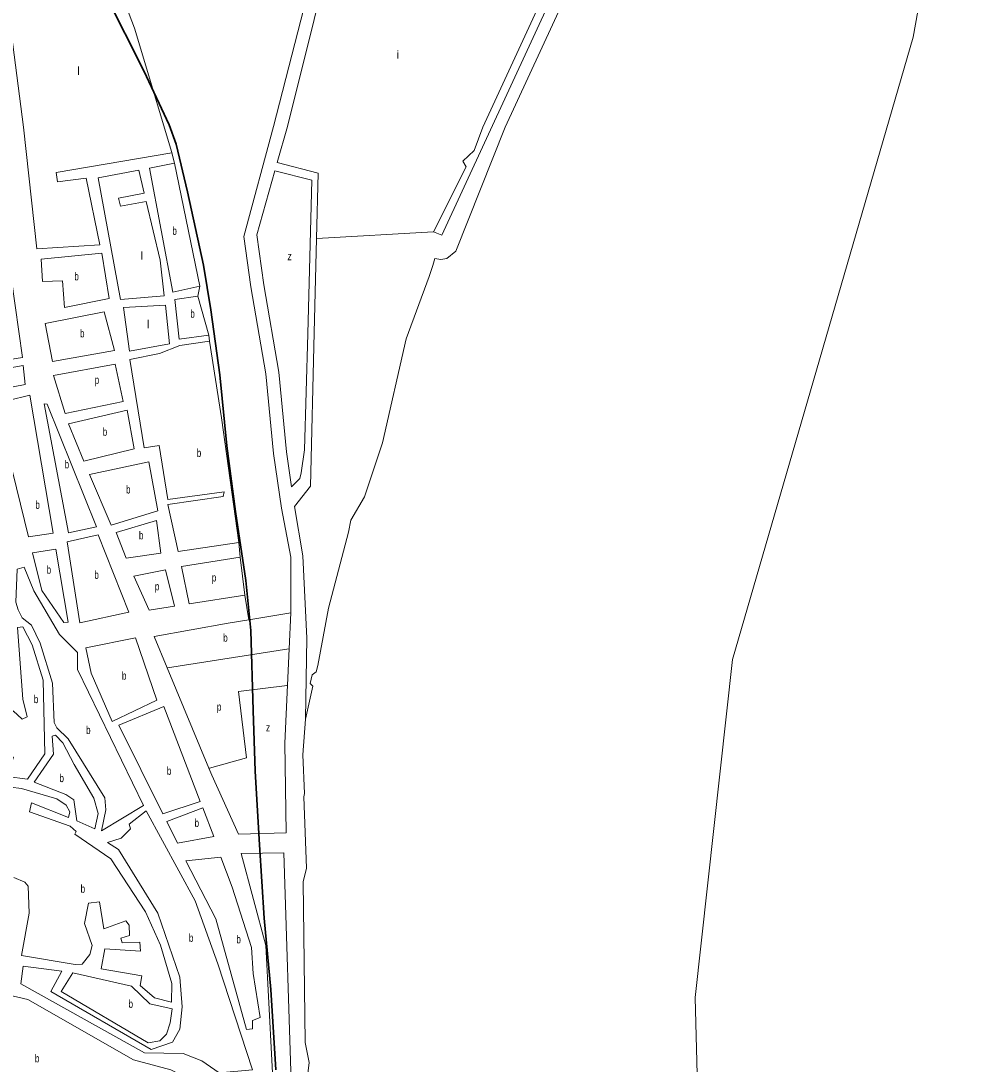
# Model space of a CAD drawing. Extents: x 639657 to 671642, y 222838 to 252123.
# Drawn here: x 649246 to 650431, y 230829 to 232133 of the extents above; entities that cross this region are included whole.
import ezdxf

# ---------------------------------------------------------------- set-up
doc = ezdxf.new("R2010")
doc.units = 0
doc.header["$LTSCALE"] = 4
for name, color, linetype, lineweight in [('1', 7, 'Continuous', 13), ('21', 7, 'Continuous', 13), ('5', 7, 'Continuous', 13), ('57', 7, 'Continuous', 35)]:
    doc.layers.add(name, color=color, linetype=linetype, lineweight=lineweight)
doc.layers.add('7', color=7, linetype='Continuous')

msp = doc.modelspace()

# ---------------------------------------------------------------- linework, layer by layer
at = {"layer": '1'}
for p, q in [((649438.357, 231955.126), (649435.192, 231967.793)), ((649541.28, 231865.64), (649563.936, 231945.516)), ((649470.009, 231801.543), (649467.77, 231788.97)), ((649482.18, 231732.54), (649445.05, 231727.09)), ((649481.26, 231740.27), (649482.18, 231732.54)), ((649257.71, 231665.2), (649286.921, 231492.626)), ((649256.111, 231487.884), (649286.921, 231492.626)), ((649260.979, 231468.111), (649290.307, 231472.624)), ((649443.105, 231469.834), (649519.069, 231480.917)), ((649519.069, 231480.917), (649520.652, 231462.709)), ((649526.191, 231415.209), (649456.923, 231404.194)), ((649526.191, 231415.209), (649531.321, 231384.416)), ((649259.79, 231377.8), (649270.686, 231355.212)), ((649424.077, 231141.872), (649470.646, 231157.402)), ((649428.786, 231132.38), (649473.78, 231149.261)), ((649246.529, 230929.234), (649401.026, 230842.89)), ((649409.489, 230847.242), (649284.125, 230919.807))]:
    msp.add_line(p, q, dxfattribs=at)
for points in [[(649762.3, 231869.13), (649772.4, 231864.93), (649940.18, 232227.89), (649998.36, 232408.27), (649997.95, 232423.52), (650058.51, 232619.37), (650064.55, 232643), (650104.58, 232932.12), (650113.04, 233010.96), (650175.02, 233792.05), (650190.2, 233935.97), (650200.75, 233955.07), (650211.5, 233964.3), (650215.81, 233978.25), (650212.82, 233991.15), (650207.837, 233999.334), (650219.35, 234019.81), (650224.822, 234038.14)], [(649702.77, 232544.411), (649668.79, 232416.28), (649562.38, 232001.06), (649525.091, 231863.401)], [(649435.192, 231967.793), (649290.77, 231943.33), (649292.43, 231931.86), (649328.02, 231936.28), (649345.19, 231853.16), (649266.36, 231847.82), (649249.9, 231999.94), (649221.67, 232216.71), (649212.68, 232270.71), (649191.78, 232361.07), (649194.31, 232402.14)], [(649566.832, 231955.727), (649579.69, 232001.06), (649679.95, 232404.23), (649852.47, 232394.09)], [(649877.62, 232406.51), (649979.89, 232407.87), (649983.96, 232397.76), (649931.38, 232233.48), (649823.94, 232000.28), (649812.92, 231970.91), (649798.63, 231957.69), (649802.98, 231950.42), (649762.3, 231869.13)], [(649438.357, 231955.126), (649407.38, 231948.77), (649436.35, 231793.89), (649470.009, 231801.543)], [(649566.832, 231955.727), (649617.981, 231942.459), (649616.022, 231860.839)], [(649584.72, 231550.58), (649595.034, 231560.876), (649596.74, 231568.11), (649600.81, 231596.95), (649605.24, 231741.89), (649610.068, 231933.751), (649563.936, 231945.516)], [(649572.085, 231523.788), (649562.183, 231592.174), (649552.709, 231691.694), (649533.778, 231800.601), (649525.091, 231863.401)], [(649584.72, 231550.58), (649578.415, 231594.121), (649568.919, 231693.871), (649549.928, 231803.121), (649541.28, 231865.64)], [(649616.022, 231860.839), (649613.19, 231742.81), (649608.486, 231551.376), (649588.26, 231526.13)], [(649481.26, 231740.27), (649444.12, 231735.04), (649438.79, 231784.66), (649467.77, 231788.97)], [(649419.283, 231602.27), (649400.72, 231599.46), (649382.65, 231709.83), (649419.77, 231717), (649445.05, 231727.09)], [(649256.111, 231487.884), (649225.91, 231610.56), (649230.69, 231658.54), (649257.71, 231665.2)], [(649419.283, 231602.27), (649430.03, 231534.77), (649500.44, 231544.14), (649499.19, 231538.54), (649430.08, 231528.54), (649443.105, 231469.834)], [(649583.954, 231393.038), (649583.648, 231462.728), (649572.085, 231523.788)], [(649602.2, 231260.14), (649603.736, 231361.371), (649598.988, 231464.287), (649588.26, 231526.13)], [(649290.307, 231472.624), (649305.75, 231381.39), (649300.38, 231380.92), (649272.55, 231421.11), (649260.979, 231468.111)], [(649520.652, 231462.709), (649447.061, 231450.834), (649456.923, 231404.194)], [(649294.91, 231365.83), (649262.89, 231420.39), (649250.62, 231450.17), (649241.82, 231447.74), (649240.22, 231406.45), (649243.09, 231396.59), (649248.11, 231386.95), (649259.79, 231377.8)], [(649583.954, 231393.038), (649581.831, 231348.027), (649579.682, 231302.45)], [(649429.416, 231324.306), (649413.12, 231363.53), (649505.4, 231380.17), (649531.321, 231384.416)], [(649399.55, 231152.37), (649347.37, 231120.37), (649352.75, 231146.84), (649351.34, 231161.66), (649305.62, 231235.66), (649291.54, 231249.31), (649288.27, 231255.94), (649285.94, 231304.93), (649270.686, 231355.212)], [(649294.91, 231365.83), (649317.23, 231343.43), (649317.39, 231322.37), (649399.55, 231152.37)], [(649518.48, 231116.29), (649485.21, 231190.01), (649481.543, 231198.836), (649429.416, 231324.306)], [(649579.682, 231302.45), (649576.28, 231230.29), (649578.03, 231117.89), (649518.48, 231116.29)], [(649470.646, 231157.402), (649425, 231275.94), (649369.09, 231252.71), (649424.077, 231141.872)], [(649191.96, 231179.96), (649247.24, 231173.3), (649291.39, 231160.76), (649303.06, 231152.47), (649307.64, 231144.12), (649305.98, 231137.02), (649259.85, 231155.35), (649257.14, 231144.15), (649308, 231126.5), (649315.79, 231119.9), (649314.1, 231116.24), (649358.83, 231085.43), (649402.12, 231019.16), (649420.93, 230977.84), (649435.28, 230929.82), (649434.61, 230906.39), (649413.51, 230911.81), (649395.76, 230927.14), (649397.6, 230939.19), (649347.03, 230948.03), (649351.34, 230973.2), (649396.06, 230970.33), (649395.33, 230981.5), (649372.99, 230980.68), (649371.22, 230986.25), (649382.37, 230989.56), (649381.84, 231002.67), (649377.49, 231008.22), (649350.28, 230998.12), (649344.8, 231032), (649331.11, 231030.25), (649325.95, 231004.59), (649335.62, 230977.16), (649332.49, 230965.96), (649323.13, 230953.85), (649314.33, 230953.35), (649247.4, 230964.86), (649256.86, 231017.79), (649255.52, 231051.31), (649251.4, 231056.43), (649237.81, 231062.34)], [(649464.11, 231032.97), (649403.26, 231145.74), (649381.69, 231129.02), (649383.67, 231123.23), (649371.94, 231111.54), (649354.58, 231106.03), (649368.4, 231097.33), (649417.82, 231017.78), (649445.32, 230937.63), (649447.98, 230900.48), (649444.98, 230872.74), (649435.87, 230856.34), (649409.489, 230847.242)], [(649428.786, 231132.38), (649442.26, 231105.22), (649487.54, 231113.53), (649473.78, 231149.261)], [(649567.46, 230690.72), (649552.53, 230977.3), (649521.71, 231092.02), (649575.25, 231092.998), (649584.745, 230793.748), (649599.555, 230443.052)], [(649401.026, 230842.89), (649449.31, 230842.05), (649472.8, 230833), (649494.2, 230817.92), (649535.85, 230821.9), (649492.68, 230954.34), (649464.11, 231032.97)], [(649246.529, 230929.234), (649249.44, 230951.55), (649297.711, 230945.357), (649284.125, 230919.807)], [(649466.79, 230805.67), (649433.78, 230821.95), (649387.27, 230834.25), (649255.36, 230909.7), (649204.99, 230921.33), (649151.23, 230925.2), (649143.7, 230873.15), (649119.54, 230804.2), (649146.68, 230796.03)]]:
    msp.add_lwpolyline(points, dxfattribs=at)
for points in [[(649400.76, 231917.62), (649393.99, 231946.29), (649343.24, 231936.8), (649370.88, 231784.56), (649425.64, 231789.07), (649420.56, 231833.75), (649403.22, 231907.22), (649371.15, 231901.31), (649368.53, 231911.5)], [(649347.64, 231842.43), (649272.05, 231834.96), (649273.56, 231807.02), (649298.7, 231808.08), (649300.9, 231774.76), (649356.9, 231785.74)], [(649248.32, 231712), (649234.65, 231809.51), (649138.69, 231796.29), (649120.43, 231768.63), (649130.98, 231694.72), (649144.204, 231654.694), (649199.595, 231674.486), (649195.639, 231703.778)], [(649382.14, 231720.14), (649374.61, 231774.7), (649427.02, 231777.47), (649432.13, 231729.35)], [(649350.77, 231769.26), (649363.43, 231720.78), (649285.989, 231707.244), (649276.66, 231754.84)], [(649249.284, 231702.137), (649251.821, 231678.444), (649224.125, 231672.902), (649218.586, 231696.653)], [(649287.186, 231689.771), (649364.186, 231703.778), (649374.472, 231657.069), (649301.673, 231642.027)], [(649275.42, 231654.16), (649305.93, 231493.17), (649341.12, 231500.54), (649279.51, 231653.77)], [(649306.14, 231629.46), (649325.21, 231582.53), (649388.27, 231597.86), (649379.5, 231646.16)], [(649359.15, 231502.61), (649332.22, 231565.82), (649406.44, 231581.88), (649417.46, 231520.7)], [(649378.18, 231461.28), (649365.67, 231493.64), (649415.84, 231508.43), (649421.32, 231467.63)], [(649304.52, 231481.76), (649320.15, 231380.43), (649381.51, 231394.02), (649343.13, 231490.66)], [(649438.463, 231401.259), (649406.705, 231396.209), (649387.714, 231438.959), (649427.279, 231446.876)], [(649248.85, 231375.35), (649242.41, 231374.87), (649249.14, 231285.3), (649254.26, 231262.98), (649248.26, 231260.14), (649237.01, 231270.37), (649222.77, 231250.27), (649194.64, 231193.74), (649219.17, 231190.28), (649227.34, 231216.35), (649237.47, 231212.77), (649229.49, 231188.64), (649254.88, 231184.97), (649276.55, 231216.73), (649274.31, 231308.71), (649260.63, 231353.09)], [(649416.55, 231283.82), (649360.68, 231257.37), (649334.19, 231317.56), (649327.5, 231349.1), (649389.93, 231361.63)], [(649289.68, 231240.05), (649285.61, 231238.73), (649287.29, 231216.39), (649263.29, 231181.38), (649302.53, 231165.79), (649312.68, 231159.42), (649316.54, 231133.02), (649338.97, 231122.88), (649343.12, 231142.04), (649337.8, 231161.55), (649313.19, 231203.48), (649298.79, 231230.45)], [(649510.39, 231050.1), (649496.55, 231087.6), (649452.809, 231083.107), (649490.29, 231010.4), (649528.57, 230872.33), (649535.87, 230873.04), (649535.79, 230883.56), (649545.65, 230887.08), (649536.82, 230942.23), (649534.63, 230974.66)], [(649405.58, 230855.67), (649296.97, 230919.7), (649311.61, 230943.02), (649384.81, 230926.41), (649407.55, 230904.46), (649435.53, 230898.24), (649432.88, 230880.6), (649428.27, 230866.59), (649419.95, 230858.15)]]:
    msp.add_lwpolyline(points, close=True, dxfattribs=at)
at = {"layer": '21'}
for p, q in [((649470.009, 231801.543), (649438.357, 231955.126)), ((649467.77, 231788.97), (649481.26, 231740.27)), ((649520.652, 231462.709), (649526.191, 231415.209)), ((649531.321, 231384.416), (649583.954, 231393.038))]:
    msp.add_line(p, q, dxfattribs=at)
for points in [[(649435.192, 231967.793), (649435.042, 231968.293), (649388.505, 232123.751), (649271.307, 232431.735)], [(649762.3, 231869.13), (649761.8, 231869.102), (649616.522, 231860.867), (649616.022, 231860.839)], [(649519.069, 231480.917), (649497.34, 231636.77), (649482.18, 231732.54)], [(649429.416, 231324.306), (649429.916, 231324.384), (649581.332, 231347.949), (649581.831, 231348.027)], [(649579.682, 231302.45), (649579.183, 231302.388), (649518.278, 231294.876), (649528.564, 231211.751), (649482.043, 231198.973), (649481.543, 231198.836)]]:
    msp.add_lwpolyline(points, dxfattribs=at)
at = {"layer": '5'}
for p, q in [((650361.63, 232112.36), (650431.47, 232508.71)), ((649948.97, 232211.11), (649851.65, 232000.28)), ((650135.58, 231334.54), (650361.63, 232112.36)), ((649851.65, 232000.28), (649789.86, 231845.02)), ((649778.76, 231836.12), (649771.47, 231834.56)), ((649789.86, 231845.02), (649778.76, 231836.12)), ((649761.21, 231827.18), (649756.59, 231813.6)), ((649763.94, 231835.79), (649761.21, 231827.18)), ((649771.47, 231834.56), (649763.94, 231835.79)), ((649756.59, 231813.6), (649727.79, 231735.33)), ((649727.79, 231735.33), (649698.3, 231605.46)), ((649698.3, 231605.46), (649676.06, 231538)), ((649676.06, 231538), (649658.67, 231509.06)), ((649658.67, 231509.06), (649655.99, 231493.78)), ((649655.99, 231493.78), (649630.75, 231398.78)), ((649630.75, 231398.78), (649617.78, 231327.11)), ((650089.21, 230912.27), (650135.58, 231334.54)), ((649610.57, 231315.45), (649607.86, 231304.89)), ((649615.48, 231319.35), (649610.57, 231315.45)), ((649617.78, 231327.11), (649615.48, 231319.35)), ((649611.54, 231301.48), (649602.2, 231260.14)), ((649607.86, 231304.89), (649611.54, 231301.48)), ((649602.2, 231260.14), (649598.68, 231215.63)), ((649598.68, 231215.63), (649601, 231167.29)), ((649601, 231167.29), (649599.96, 231163.2)), ((649599.96, 231163.2), (649603.46, 231074.05)), ((649603.46, 231074.05), (649599.09, 231056.82)), ((649599.09, 231056.82), (649601.55, 230855.94)), ((650089.21, 230912.27), (650099.96, 230494.39)), ((649601.55, 230855.94), (649606.91, 230830.85)), ((649606.91, 230830.85), (649601.66, 230788.48))]:
    msp.add_line(p, q, dxfattribs=at)
at = {"layer": '57'}
for points in [[(649431.73, 232002.995), (649399.994, 232070.308), (649353.025, 232164.294), (649236.203, 232405.189), (649089.828, 232739.384), (648914.202, 233126.457), (648685.944, 233640.163), (648499.009, 234038.457), (648378.361, 234308.787), (648275.477, 234548.58), (648171.383, 234786.42), (648107.014, 234960.761), (648078.134, 235089.132), (648042.869, 235271.292), (648019.786, 235394.046), (648011.928, 235560.15), (648011.719, 235757.044), (648014.054, 235904.557)], [(649431.73, 232002.995), (649440.616, 231978.863), (649454.58, 231919.17), (649474.891, 231827.725), (649483.777, 231771.841), (649495.202, 231690.557), (649503.934, 231601.783), (649514.505, 231519.66), (649527.573, 231433.368), (649533.921, 231371.134), (649536.804, 231271.089), (649539.157, 231195.301), (649544.82, 231103.249), (649550.484, 231011.197), (649558.675, 230922.164), (649565.023, 230821.828)]]:
    msp.add_lwpolyline(points, dxfattribs=at)

# ---------------------------------------------------------------- texts
at = {"layer": '7'}
for s, p in [('i', (649716.103, 232085.755)), ('l', (649317.081, 232065.471)), ('l', (649396.211, 231834.305)), ('l', (649404.124, 231748.805))]:
    msp.add_text(s, height=10, dxfattribs=at).set_placement(p)
for s, width, p in [('b', 0.75, (649435.837, 231865.519)), ('z', 0.8, (649579.634, 231833.828)), ('b', 0.75, (649313.321, 231808.595)), ('b', 0.75, (649458.231, 231762.005)), ('b', 0.75, (649320.443, 231737.345)), ('p', 0.75, (649338.725, 231679.209)), ('b', 0.75, (649348.779, 231614.345)), ('b', 0.75, (649466.306, 231587.925)), ('b', 0.75, (649301.197, 231573.665)), ('b', 0.75, (649377.922, 231542.245)), ('b', 0.75, (649264.611, 231523.06)), ('b', 0.75, (649394.036, 231484.855)), ('b', 0.75, (649278.697, 231441.98)), ('b', 0.75, (649338.334, 231435.545)), ('p', 0.75, (649485.116, 231432.208)), ('p', 0.75, (649413.899, 231421.125)), ('b', 0.75, (649499.359, 231357)), ('b', 0.75, (649372.751, 231309.5)), ('b', 0.75, (649262.662, 231280.16)), ('p', 0.75, (649491.446, 231270.708)), ('b', 0.75, (649327.997, 231241.55)), ('z', 0.8, (649552.73, 231244.827)), ('b', 0.75, (649428.891, 231190.58)), ('b', 0.75, (649294.73, 231181.465)), ('b', 0.75, (649463.557, 231125.55)), ('b', 0.75, (649321.139, 231043.175)), ('b', 0.75, (649456.423, 230981.83)), ('b', 0.75, (649515.827, 230979.965)), ('b', 0.75, (649381.028, 230899.345)), ('b', 0.75, (649263.979, 230831.155))]:
    msp.add_text(s, height=10, dxfattribs=dict(at, width=width)).set_placement(p)

doc.saveas('drawing.dxf')
